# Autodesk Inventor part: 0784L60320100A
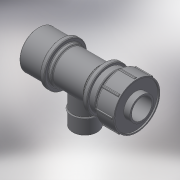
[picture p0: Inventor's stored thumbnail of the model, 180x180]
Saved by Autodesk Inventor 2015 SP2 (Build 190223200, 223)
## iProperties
Created: 2018-02
Part Number: 0784L60320100A
Material: Generic
Description: PLASSON MODULAR MALE TEE 32-1"-32
Document SubType Name: Modeling
Designer: KIM
Density: 1 g/cm^3
Appearance: Default
Author: KIM
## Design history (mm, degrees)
derived "0784L6.ipt"
feature "Solid1::0784L6.ipt"
feature "Solid2::0784L6.ipt"
tag "TaggingFeature1"
body "Solid1"
other parameters: "d26" = 38.55665, "d51" = 2, "d52" = 3.2, "d54" = 0, "d55" = 2, "d56" = 1, "d58" = 360 deg, "d60" = 1, "d63" = 1, "d65" = 0, "d67" = 0, "d69" = 139, "d70" = 58, "d71" = 33.249, "d72" = 32, "d73" = 62.08, "d74" = 51, "d75" = 31, "d76" = 58.88, "d77" = 33, "d79" = 29.76, "d80" = 27.2, "d81" = 32, "d82" = 6.2, "d83" = 57.6, "d84" = 57.6, "d86" = 48, "d88" = 51.2, "d89" = 44.8, "d90" = 8.25, "d91" = 31.35, "d92" = 54.4, "d93" = 36.3, "d94" = 29.7, "d95" = 6.6, "d96" = 44.55, "d97" = 41.7, "d98" = 44.8, "d99" = 32, "d100" = 28.8, "d102" = 24.93675, "d103" = 36.5739, "d104" = 22, "E_" = 64, "H_" = 139, "l_1" = 33, "A_" = 58, "d_" = 1, "R_" = 33.249, "ODP_" = 51, "LPT_" = 31, "SOD_" = 32
